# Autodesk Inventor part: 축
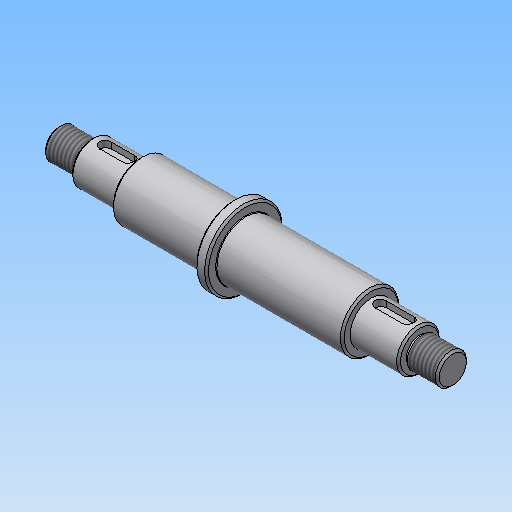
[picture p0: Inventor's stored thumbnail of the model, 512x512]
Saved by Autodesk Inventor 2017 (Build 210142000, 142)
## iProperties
Created: 2021-06
Part Number: 축
Material: 강철, 연강
Document SubType Name: Modeling
Designer: mdu
Density: 1 g/cm^3
Appearance: 흰색
CustomPartVersion: 1
Author: mdu
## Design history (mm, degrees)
sketch "주 스케치"
  geometry: L1 (0, 0)-(203, 0) reference; L2 (0, 0)-(0, 8); L3 (0, 8)-(17, 8); L4 (17, 8)-(17, 11); L5 (17, 11)-(42, 11); L6 (42, 11)-(42, 15); L7 (42, 15)-(90, 15); L8 (90, 15)-(90, 20); L9 (96, 20)-(96, 15); L10 (90, 20)-(96, 20); L11 (161, 15)-(161, 11); L12 (96, 15)-(161, 15); L13 (186, 11)-(186, 8); L14 (161, 11)-(186, 11); L15 (203, 8)-(203, 0); L16 (186, 8)-(203, 8)
  constraints: 32 end point, 9 horizontal, 8 vertical
  dimensions: "d3" = 16 diameter of L3 L1 (derived); "d4" = 22 diameter of L5 L1 (derived); "d5" = 30 diameter of L7 L1 (derived); "d6" = 40 diameter of L10 L1 (derived); "d7" = 30 diameter of L12 L1 (derived); "d8" = 22 diameter of L14 L1 (derived); "d9" = 16 diameter of L16 L1 (derived)
revolve "회전1" sketch "주 스케치" stored, may be unused: angle "d10" = 0 deg
chamfer "모따기1" distance "d11" = 1; stored, may be unused: second distance "d12" = 1, angle "d13" = 45 deg
chamfer "모따기2" distance "d14" = 1; stored, may be unused: second distance "d15" = 1, angle "d16" = 45 deg
node "키홈1"
chamfer "모따기3" distance "d17" = 1; stored, may be unused: second distance "d18" = 1, angle "d19" = 45 deg
fillet "모깎기1" dims "d20" = 0.3
chamfer "모따기4" distance "d21" = 1; stored, may be unused: second distance "d22" = 1, angle "d23" = 45 deg
chamfer "모따기5" distance "d24" = 1; stored, may be unused: second distance "d25" = 1, angle "d26" = 45 deg
fillet "모깎기2" dims "d27" = 0.3
chamfer "모따기6" distance "d28" = 1; stored, may be unused: second distance "d29" = 1, angle "d30" = 45 deg
chamfer "모따기7" distance "d31" = 1; stored, may be unused: second distance "d32" = 1, angle "d33" = 45 deg
node "키홈2"
chamfer "모따기8" distance "d34" = 1; stored, may be unused: second distance "d35" = 1, angle "d36" = 45 deg
sketch "스케치3"
  geometry: L1 (1, 8)-(17, 8) reference; L2 (17, -10)-(17, 10) reference; L3 (186, 10)-(186, -10) reference; L4 (186, 8)-(202, 8) reference; L5 (203, 7)-(203, -7) reference; L6 (0, 0)-(203, 0); L7 (17, 8)-(15.5, 8); L8 (15.5, 8)-(15.5, 7); L9 (15.5, 7)-(17, 7); L10 (17, 7)-(17, 8); L11 (186, 8)-(187.5, 8); L12 (187.5, 8)-(187.5, 7); L13 (187.5, 7)-(186, 7); L14 (186, 7)-(186, 8)
  constraints: 18 end point, 4 parallel, 2 horizontal, 2 perpendicular, 1 midpoint
  dimensions: "d37" = 14 diameter of L13 L6; "d39" = 1.5 distance of L12.end L13.end; "d40" = 14 diameter of L9 L6; "d41" = 1.5 distance of L8.end L9.end
revolve "회전2" sketch "스케치3" stored, may be unused: angle "d42" = 90 deg
feature "스레드1" dims "d43" = 10, "d44" = 0
feature "스레드2" dims "d45" = 10, "d46" = 0
sketch "스케치4"
  geometry: L1 (186, 7)-(186, -7) reference; L2 (186, 10)-(186, -10) reference; L3 (161, -11)-(185, -11) reference; L4 (165, -11)-(165, -9); L5 (165, -9)-(167, -11); L6 (165, -11)-(167, -11); 1 further point
  constraints: 6 end point, 2 point on line, 1 collinear, 1 perpendicular
  dimensions: "d47" = 21 distance from line of L2 L4.start; "d48" = 4 diameter of L5.end L4; "d49" = 45 deg angle of L4 L5
revolve "회전3" sketch "스케치4" stored, may be unused: angle "d50" = 90 deg
node "솔리드1"
feature "iFeature3:1"
feature "iFeature3:2"
node "투영된 루프1"
other parameters: "d0" = 0, "d1" = 0, "d2" = 0
